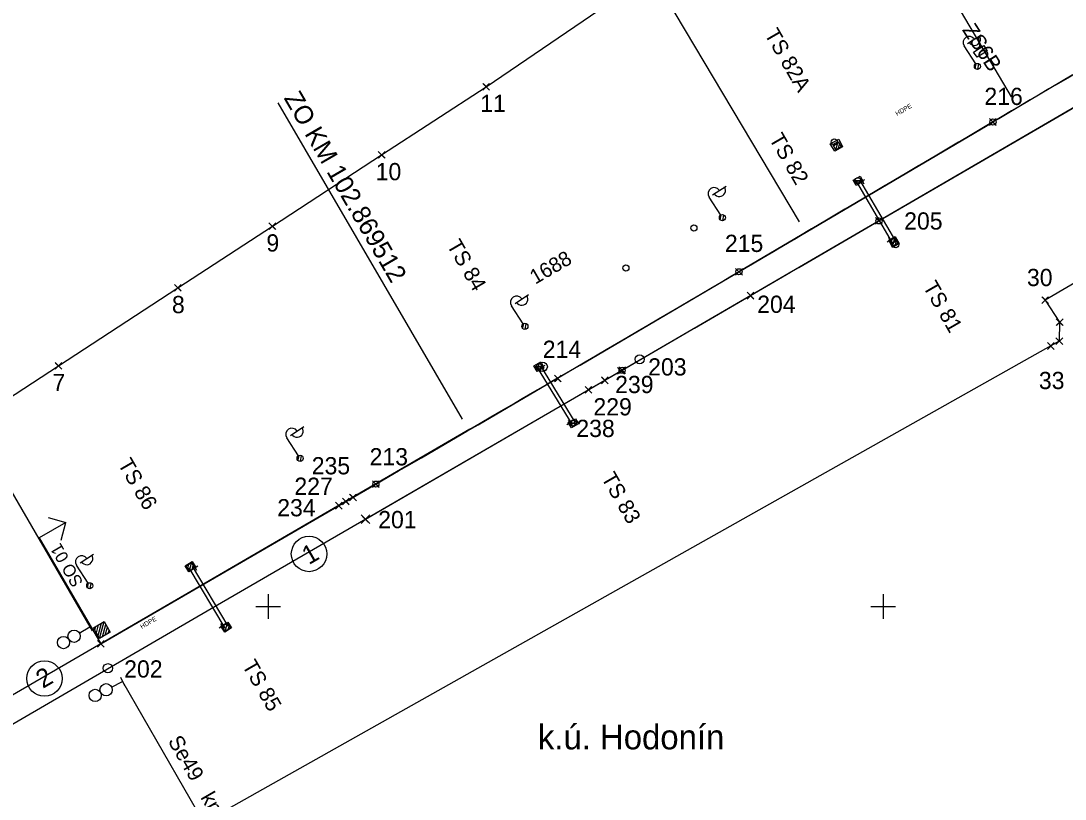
# Model space of a CAD drawing. Extents: x -566182 to -565305, y -1203073 to -1202401.
# Drawn here: x -566040.2 to -565870.4, y -1202931.3 to -1202804.8 of the extents above; entities that cross this region are included whole.
import ezdxf

# ---------------------------------------------------------------- set-up
doc = ezdxf.new("R2010")
doc.units = 0
for name, color, linetype in [('Implicitní', 7, 'Continuous'), ('LÁTAL_SVRŠEK', 7, 'Continuous'), ('PODÉLNÝ PROFIL POPIS+TENKÁ', 7, 'Continuous'), ('SZDC', 7, 'Continuous'), ('Vrstva 1', 7, 'Continuous'), ('Vrstva 10', 7, 'Continuous'), ('Vrstva 12', 7, 'Continuous'), ('Vrstva 13', 7, 'Continuous'), ('Vrstva 24', 7, 'Continuous'), ('Vrstva 25', 7, 'Continuous'), ('Vrstva 28', 7, 'Continuous'), ('Vrstva 39', 7, 'Continuous'), ('Vrstva 40', 7, 'Continuous'), ('Vrstva 42', 7, 'Continuous'), ('Vrstva 5', 7, 'Continuous'), ('Vrstva 6', 7, 'Continuous'), ('Vrstva 60', 7, 'Continuous'), ('Vrstva 62', 7, 'Continuous'), ('Vrstva 63', 7, 'Continuous'), ('Vrstva 8', 7, 'Continuous'), ('Vrstva 9', 7, 'Continuous')]:
    doc.layers.add(name, color=color, linetype=linetype)

# ---------------------------------------------------------------- blocks, each defined once
blk = doc.blocks.new('ODPOJ')
at = {"layer": 'Vrstva 62'}
blk.add_circle((0, 0), 5, dxfattribs=at)
blk = doc.blocks.new('C513')
at = {"layer": 'Vrstva 6'}
blk.add_circle((0, 0), 7.5, dxfattribs=at)
blk = doc.blocks.new('C691')
at = {"layer": 'Vrstva 12'}
for p, q in [((-5, 0), (5, 0)), ((0, 5), (0, -5))]:
    blk.add_line(p, q, dxfattribs=at)
blk = doc.blocks.new('C669')
at = {"layer": 'Vrstva 6'}
for p, q in [((0, 5), (0, 40)), ((7, 40), (33, 40)), ((-5, -1), (1, 5)), ((-2, -4), (4, 2))]:
    blk.add_line(p, q, dxfattribs=at)
blk.add_circle((0, 0), 5, dxfattribs=at)
blk.add_circle((0, 0), 5, dxfattribs=at)
for centre, start, end in [((10, 40), 0.0001, 180.0001), ((20, 39.9), 179.2975, 0.7026)]:
    blk.add_arc(centre, 10, start, end, dxfattribs=at)
blk = doc.blocks.new('C202_1')
at = {"layer": 'Vrstva 8'}
blk.add_lwpolyline([(-9.5, 0.3), (-10.2, 10.1), (10.1, 10.2), (9.5, -0.3), (-9.5, 0.3)], dxfattribs=at)
blk = doc.blocks.new('C661')
at = {"layer": 'Vrstva 12'}
for p, q in [((-5, 0.3), (-0.3, 5)), ((-5, -5), (5, 5)), ((0.3, -5), (5, -0.3))]:
    blk.add_line(p, q, dxfattribs=at)
blk.add_lwpolyline([(-5, 5), (5, 5), (5, -5), (-5, -5)], close=True, dxfattribs=at)
blk.add_lwpolyline([(-5, 5), (5, 5), (5, -5), (-5, -5), (-5, 5)], dxfattribs=at)
blk = doc.blocks.new('C661_1')
at = {"layer": 'Vrstva 12'}
for p, q in [((-5, 0.3), (-0.3, 5)), ((-5, -5), (5, 5)), ((0.3, -5), (5, -0.3))]:
    blk.add_line(p, q, dxfattribs=at)
blk.add_lwpolyline([(-5, 5), (5, 5), (5, -5), (-5, -5)], close=True, dxfattribs=at)
blk.add_lwpolyline([(-5, 5), (5, 5), (5, -5), (-5, -5), (-5, 5)], dxfattribs=at)
blk = doc.blocks.new('C661_2')
at = {"layer": 'Vrstva 12'}
for p, q in [((-5, 0.3), (-0.3, 5)), ((-5, -5), (5, 5)), ((0.3, -5), (5, -0.3))]:
    blk.add_line(p, q, dxfattribs=at)
blk.add_lwpolyline([(-5, 5), (5, 5), (5, -5), (-5, -5)], close=True, dxfattribs=at)
blk.add_lwpolyline([(-5, 5), (5, 5), (5, -5), (-5, -5), (-5, 5)], dxfattribs=at)
blk = doc.blocks.new('C651')
at = {"layer": 'Vrstva 28'}
for p, q in [((-10, -4.1), (-5.9, 0)), ((-10, -9.4), (-0.6, 0)), ((-10, -14.7), (4.7, 0)), ((-10, -20), (10, 0)), ((-4.7, -20), (10, -5.3)), ((0.6, -20), (10, -10.6)), ((5.9, -20), (10, -15.9))]:
    blk.add_line(p, q, dxfattribs=at)
blk.add_lwpolyline([(-10, 0), (10, 0), (10, -20), (-10, -20)], close=True, dxfattribs=at)
blk.add_lwpolyline([(-10, 0), (10, 0), (10, -20), (-10, -20)], close=True, dxfattribs=at)
blk.add_lwpolyline([(-10, 0), (10, 0), (10, -20), (-10, -20), (-10, 0)], dxfattribs=at)
blk.add_lwpolyline([(-10, 0), (10, 0), (10, -20), (-10, -20), (-10, 0)], dxfattribs=at)
blk = doc.blocks.new('C569_2')
at = {"layer": 'Vrstva 24'}
for p, q in [((0, -7.5), (0, 7.5)), ((20, 0), (0, 0))]:
    blk.add_line(p, q, dxfattribs=at)
for centre in [(30, 0), (50, 0)]:
    blk.add_circle(centre, 10, dxfattribs=at)
blk = doc.blocks.new('C569_3')
at = {"layer": 'Vrstva 24'}
for p, q in [((0, -7.5), (0, 7.5)), ((20, 0), (0, 0))]:
    blk.add_line(p, q, dxfattribs=at)
for centre in [(30, 0), (50, 0)]:
    blk.add_circle(centre, 10, dxfattribs=at)
blk = doc.blocks.new('ODPOJ_1')
at = {"layer": 'Vrstva 40'}
blk.add_circle((0, 0), 5, dxfattribs=at)
blk = doc.blocks.new('C562')
at = {"layer": 'Vrstva 12'}
for p, q in [((-5, 0), (5, 0)), ((-4, -3), (-1, 0)), ((-0.6, -5), (4.3, 0))]:
    blk.add_line(p, q, dxfattribs=at)
blk.add_lwpolyline([(5, 0), (-5, 0)], dxfattribs=at)
blk.add_circle((0, 0), 5.03, dxfattribs=at)
blk.add_arc((0, 0), 5.03, 180, 0, dxfattribs=at)
blk = doc.blocks.new('POINT_DISPLAY')
at = {"layer": 'Implicitní'}
for p, q in [((-0.7, -0.7), (0.7, 0.7)), ((-0.7, 0.7), (0.7, -0.7))]:
    blk.add_line(p, q, dxfattribs=at)

msp = doc.modelspace()

# ---------------------------------------------------------------- linework, layer by layer
at = {"layer": 'LÁTAL_SVRŠEK'}
for p, q in [((-565900.69, -1202837.33), (-565859.02, -1202813.09)), ((-565900.69, -1202837.33), (-565859.02, -1202813.09)), ((-565882.15, -1202821.26), (-565923.45, -1202845.6)), ((-565923.45, -1202845.6), (-565882.15, -1202821.26)), ((-565984.2, -1202885.83), (-565942.45, -1202861.6)), ((-566027.23, -1202906.08), (-565982.49, -1202880.12))]:
    msp.add_line(p, q, dxfattribs=at)
for centre in [(-565882.15, -1202821.26), (-565900.69, -1202837.33), (-565923.45, -1202845.6), (-565942.45, -1202861.6), (-565982.49, -1202880.12)]:
    msp.add_circle(centre, 0.5, dxfattribs=at)
for centre, radius, start, end in [((-560804.84, -1211436.41), 10000, 120.189547, 120.512837), ((-591042.76, -1159618.4), 50000, 300.132814, 300.188159), ((-571000.77, -1194230.45), 10000, 300.120974, 300.512837)]:
    msp.add_arc(centre, radius, start, end, dxfattribs=at)
at = {"layer": 'PODÉLNÝ PROFIL POPIS+TENKÁ'}
for centre in [(-565993.37, -1202891.47), (-566036.39, -1202911.72)]:
    msp.add_circle(centre, 2.88, dxfattribs=at)
at = {"layer": 'SZDC'}
for points in [[(-566109.86, -1202908.94), (-566097.96, -1202902.03), (-566084.51, -1202894.21), (-566065.16, -1202881.19), (-566062.89, -1202879.66), (-566050.93, -1202871.86), (-566034.12, -1202860.89), (-566014.69, -1202848.22), (-565999.33, -1202838.2), (-565981.56, -1202826.61), (-565964.56, -1202815.52), (-565946.25, -1202803.07), (-565943.74, -1202801.57), (-565935.57, -1202796.69), (-565927.13, -1202791.65), (-565924.54, -1202790.1), (-565905.03, -1202778.89), (-565894.6, -1202771.96), (-565883.49, -1202764.57), (-565860.68, -1202749.5), (-565834.73, -1202732.72)], [(-565859.38, -1202962.26), (-565861.03, -1202936.37), (-565855.35, -1202900.62), (-565842.42, -1202864.28), (-565828.48, -1202833.86), (-565823.01, -1202820.65), (-565873.65, -1202850.2), (-565871.3, -1202853.81), (-565871.36, -1202856.88), (-565872.74, -1202857.66), (-566063.99, -1202965.17)]]:
    msp.add_lwpolyline(points, dxfattribs=at)
at = {"layer": 'Vrstva 1'}
for p, q in [((-566032.9, -1202886.33), (-566037.23, -1202888.84)), ((-566035.8, -1202885.56), (-566032.9, -1202886.33)), ((-566033.67, -1202889.23), (-566032.9, -1202886.33)), ((-566037.23, -1202888.84), (-566027.23, -1202906.08))]:
    msp.add_line(p, q, dxfattribs=at)
at = {"layer": 'Vrstva 10'}
for p, q in [((-565908.63, -1202824.83), (-565907.23, -1202824.05)), ((-565907.88, -1202826), (-565908.63, -1202824.83)), ((-565906.59, -1202825.27), (-565907.88, -1202826)), ((-565907.23, -1202824.05), (-565906.59, -1202825.27)), ((-565904.89, -1202830.72), (-565903.76, -1202830.04)), ((-565903.76, -1202830.04), (-565903.28, -1202830.9)), ((-565904.41, -1202831.56), (-565904.89, -1202830.72)), ((-565903.28, -1202830.9), (-565904.41, -1202831.56)), ((-565899.1, -1202840.45), (-565898.07, -1202839.85)), ((-565898.46, -1202841.63), (-565899.1, -1202840.45)), ((-565898.07, -1202839.85), (-565897.38, -1202841.02)), ((-565897.38, -1202841.02), (-565898.46, -1202841.63)), ((-565956.82, -1202860.91), (-565955.68, -1202860.24)), ((-565956.28, -1202861.79), (-565956.82, -1202860.91)), ((-565955.68, -1202860.24), (-565955.21, -1202861.14)), ((-565955.21, -1202861.14), (-565956.28, -1202861.79)), ((-565951.21, -1202870.12), (-565950.05, -1202869.5)), ((-565950.05, -1202869.5), (-565949.57, -1202870.3)), ((-565950.7, -1202870.96), (-565951.21, -1202870.12)), ((-565949.57, -1202870.3), (-565950.7, -1202870.96)), ((-566013.49, -1202893.38), (-566012.36, -1202892.67)), ((-566012.92, -1202894.4), (-566013.49, -1202893.38)), ((-566012.36, -1202892.67), (-566011.78, -1202893.69)), ((-566011.78, -1202893.69), (-566012.92, -1202894.4)), ((-566007.72, -1202903.2), (-566006.59, -1202902.54)), ((-566007.08, -1202904.19), (-566007.72, -1202903.2)), ((-566005.96, -1202903.5), (-566007.08, -1202904.19)), ((-566006.59, -1202902.54), (-566005.96, -1202903.5))]:
    msp.add_line(p, q, dxfattribs=at)
at = {"layer": 'Vrstva 12'}
for points in [[(-565904.36, -1202830.96), (-565898.53, -1202840.91)], [(-565903.84, -1202830.66), (-565898.01, -1202840.61)], [(-565955.74, -1202860.87), (-565950.12, -1202870.04)], [(-565956.25, -1202861.18), (-565950.64, -1202870.36)], [(-566012.91, -1202893.74), (-566007.07, -1202903.52)], [(-566012.39, -1202893.43), (-566006.56, -1202903.21)]]:
    msp.add_lwpolyline(points, dxfattribs=at)
at = {"layer": 'Vrstva 5'}
for p, q in [((-566000, -1202898), (-566000, -1202902)), ((-565900, -1202898), (-565900, -1202902)), ((-566002, -1202900), (-565998, -1202900)), ((-565902, -1202900), (-565898, -1202900))]:
    msp.add_line(p, q, dxfattribs=at)
at = {"layer": 'Vrstva 6'}
for points in [[(-566068.74, -1202934.92), (-566067.2, -1202934.01), (-566009.26, -1202900.35), (-565952.55, -1202867.42), (-565900.78, -1202837.32), (-565844.77, -1202804.78), (-565792.03, -1202774.14)], [(-565967.23, -1202871.18), (-566010.28, -1202896.21), (-566069.32, -1202930.5), (-566070.86, -1202931.4)]]:
    msp.add_lwpolyline(points, dxfattribs=at)
for centre, radius, start, end in [((-561050.64, -1211005.49), 9503.95, 120.13635, 120.525886), ((-524776.56, -1272604.54), 80989.97, 120.4966194, 120.5251694), ((-572122.69, -1192292.3), 12239.38, 300.193528, 300.489147)]:
    msp.add_arc(centre, radius, start, end, dxfattribs=at)
at = {"layer": 'Vrstva 60'}
for p, q in [((-565879.13, -1202817.16), (-565911.63, -1202762.03)), ((-565913.59, -1202837.48), (-565953.43, -1202770.71)), ((-565964.11, -1202815.97), (-565965.11, -1202814.97)), ((-565964.11, -1202815.07), (-565965.11, -1202816.07)), ((-565965.01, -1202815.97), (-565964.01, -1202814.97)), ((-565965.01, -1202815.07), (-565964.01, -1202816.07)), ((-565964.56, -1202815.52), (-565964.56, -1202815.52)), ((-565968.41, -1202869.55), (-565998.4, -1202818.13)), ((-565881.7, -1202821.71), (-565882.7, -1202820.71)), ((-565881.7, -1202820.81), (-565882.7, -1202821.81)), ((-565882.6, -1202821.71), (-565881.6, -1202820.71)), ((-565882.6, -1202820.81), (-565881.6, -1202821.81)), ((-565882.15, -1202821.26), (-565882.15, -1202821.26)), ((-565981.11, -1202827.06), (-565982.11, -1202826.06)), ((-565981.11, -1202826.16), (-565982.11, -1202827.16)), ((-565982.01, -1202827.06), (-565981.01, -1202826.06)), ((-565982.01, -1202826.16), (-565981.01, -1202827.16)), ((-565981.56, -1202826.61), (-565981.56, -1202826.61)), ((-565900.24, -1202837.78), (-565901.24, -1202836.78)), ((-565900.24, -1202836.88), (-565901.24, -1202837.88)), ((-565901.14, -1202837.78), (-565900.14, -1202836.78)), ((-565901.14, -1202836.88), (-565900.14, -1202837.88)), ((-565900.69, -1202837.33), (-565900.69, -1202837.33)), ((-565998.88, -1202838.65), (-565999.88, -1202837.65)), ((-565998.88, -1202837.75), (-565999.88, -1202838.75)), ((-565999.78, -1202838.65), (-565998.78, -1202837.65)), ((-565999.78, -1202837.75), (-565998.78, -1202838.75)), ((-565999.33, -1202838.2), (-565999.33, -1202838.2)), ((-565923, -1202846.05), (-565924, -1202845.05)), ((-565923, -1202845.15), (-565924, -1202846.15)), ((-565923.9, -1202846.05), (-565922.9, -1202845.05)), ((-565923.9, -1202845.15), (-565922.9, -1202846.15)), ((-565923.45, -1202845.6), (-565923.45, -1202845.6)), ((-566014.24, -1202848.67), (-566015.24, -1202847.67)), ((-566014.24, -1202847.77), (-566015.24, -1202848.77)), ((-566015.14, -1202848.67), (-566014.14, -1202847.67)), ((-566015.14, -1202847.77), (-566014.14, -1202848.77)), ((-566014.69, -1202848.22), (-566014.69, -1202848.22)), ((-565921.11, -1202849.93), (-565922.11, -1202848.93)), ((-565921.11, -1202849.03), (-565922.11, -1202850.03)), ((-565922.01, -1202849.93), (-565921.01, -1202848.93)), ((-565922.01, -1202849.03), (-565921.01, -1202850.03)), ((-565921.56, -1202849.48), (-565921.56, -1202849.48)), ((-565873.2, -1202850.65), (-565874.2, -1202849.65)), ((-565873.2, -1202849.75), (-565874.2, -1202850.75)), ((-565874.1, -1202850.65), (-565873.1, -1202849.65)), ((-565874.1, -1202849.75), (-565873.1, -1202850.75)), ((-565873.65, -1202850.2), (-565873.65, -1202850.2)), ((-566058.78, -1202852.05), (-566029.01, -1202903.3)), ((-565870.85, -1202854.26), (-565871.85, -1202853.26)), ((-565870.85, -1202853.36), (-565871.85, -1202854.36)), ((-565871.75, -1202854.26), (-565870.75, -1202853.26)), ((-565871.75, -1202853.36), (-565870.75, -1202854.36)), ((-565871.3, -1202853.81), (-565871.3, -1202853.81)), ((-565872.29, -1202858.11), (-565873.29, -1202857.11)), ((-565872.29, -1202857.21), (-565873.29, -1202858.21)), ((-565873.19, -1202858.11), (-565872.19, -1202857.11)), ((-565873.19, -1202857.21), (-565872.19, -1202858.21)), ((-565872.74, -1202857.66), (-565872.74, -1202857.66)), ((-565870.91, -1202857.33), (-565871.91, -1202856.33)), ((-565870.91, -1202856.43), (-565871.91, -1202857.43)), ((-565871.81, -1202857.33), (-565870.81, -1202856.33)), ((-565871.81, -1202856.43), (-565870.81, -1202857.43)), ((-565871.36, -1202856.88), (-565871.36, -1202856.88)), ((-566033.67, -1202861.34), (-566034.67, -1202860.34)), ((-566033.67, -1202860.44), (-566034.67, -1202861.44)), ((-566034.57, -1202861.34), (-566033.57, -1202860.34)), ((-566034.57, -1202860.44), (-566033.57, -1202861.44)), ((-566034.12, -1202860.89), (-566034.12, -1202860.89)), ((-565942, -1202862.05), (-565943, -1202861.05)), ((-565942.9, -1202862.05), (-565941.9, -1202861.05)), ((-565952.46, -1202863.41), (-565953.46, -1202862.41)), ((-565952.46, -1202862.51), (-565953.46, -1202863.51)), ((-565953.36, -1202863.41), (-565952.36, -1202862.41)), ((-565953.36, -1202862.51), (-565952.36, -1202863.51)), ((-565944.83, -1202863.69), (-565945.83, -1202862.69)), ((-565944.83, -1202862.79), (-565945.83, -1202863.79)), ((-565945.73, -1202863.69), (-565944.73, -1202862.69)), ((-565945.73, -1202862.79), (-565944.73, -1202863.79)), ((-565942.18, -1202862.16), (-565943.18, -1202861.16)), ((-565942.18, -1202861.26), (-565943.18, -1202862.26)), ((-565943.08, -1202862.16), (-565942.08, -1202861.16)), ((-565943.08, -1202861.26), (-565942.08, -1202862.26)), ((-565942, -1202861.15), (-565943, -1202862.15)), ((-565942.9, -1202861.15), (-565941.9, -1202862.15)), ((-565942.63, -1202861.71), (-565942.63, -1202861.71)), ((-565942.45, -1202861.6), (-565942.45, -1202861.6)), ((-565952.91, -1202862.96), (-565952.91, -1202862.96)), ((-565947.48, -1202865.23), (-565948.48, -1202864.23)), ((-565947.48, -1202864.33), (-565948.48, -1202865.33)), ((-565948.39, -1202865.23), (-565947.39, -1202864.23)), ((-565948.39, -1202864.33), (-565947.39, -1202865.33)), ((-565945.28, -1202863.24), (-565945.28, -1202863.24)), ((-565947.94, -1202864.78), (-565947.94, -1202864.78)), ((-565982.04, -1202880.57), (-565983.04, -1202879.57)), ((-565982.04, -1202879.67), (-565983.04, -1202880.67)), ((-565982.94, -1202880.57), (-565981.94, -1202879.57)), ((-565982.94, -1202879.67), (-565981.94, -1202880.67)), ((-565982.49, -1202880.12), (-565982.49, -1202880.12)), ((-565988.07, -1202884.07), (-565989.07, -1202883.07)), ((-565988.07, -1202883.17), (-565989.07, -1202884.17)), ((-565988.97, -1202884.07), (-565987.97, -1202883.07)), ((-565988.97, -1202883.17), (-565987.97, -1202884.17)), ((-565986.92, -1202883.4), (-565987.92, -1202882.4)), ((-565986.92, -1202882.5), (-565987.92, -1202883.5)), ((-565987.82, -1202883.4), (-565986.82, -1202882.4)), ((-565987.82, -1202882.5), (-565986.82, -1202883.5)), ((-565987.37, -1202882.95), (-565987.37, -1202882.95)), ((-565985.77, -1202882.74), (-565986.77, -1202881.74)), ((-565985.77, -1202881.83), (-565986.77, -1202882.83)), ((-565986.67, -1202882.74), (-565985.67, -1202881.74)), ((-565986.67, -1202881.83), (-565985.67, -1202882.83)), ((-565986.22, -1202882.28), (-565986.22, -1202882.28)), ((-565988.52, -1202883.62), (-565988.52, -1202883.62)), ((-565983.75, -1202886.28), (-565984.75, -1202885.28)), ((-565983.75, -1202885.38), (-565984.75, -1202886.38)), ((-565984.65, -1202886.28), (-565983.65, -1202885.28)), ((-565984.65, -1202885.38), (-565983.65, -1202886.38)), ((-565984.2, -1202885.83), (-565984.2, -1202885.83)), ((-566026.78, -1202906.53), (-566027.78, -1202905.53)), ((-566026.78, -1202905.63), (-566027.78, -1202906.63)), ((-566027.68, -1202906.53), (-566026.68, -1202905.53)), ((-566027.68, -1202905.63), (-566026.68, -1202906.63)), ((-566027.23, -1202906.08), (-566027.23, -1202906.08)), ((-566023.69, -1202912.19), (-565996.16, -1202959.95))]:
    msp.add_line(p, q, dxfattribs=at)
at = {"layer": 'Vrstva 63'}
msp.add_line((-565955.41, -1202861.06), (-565955.32, -1202861.01), dxfattribs=at)
msp.add_circle((-565955.37, -1202861.04), 0.756, dxfattribs=at)

# ---------------------------------------------------------------- block references
at = {"layer": 'LÁTAL_SVRŠEK'}
msp.add_blockref('POINT_DISPLAY', (-565984.2, -1202885.83), dxfattribs=at)
at = {"layer": 'Vrstva 12'}
for name, p, xscale, yscale, rotation in [('C661_2', (-565907.53, -1202825.08), 0.10000006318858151, 0.10000006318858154, 29.57266490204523), ('C691', (-565903.4, -1202830.85), 0.09999990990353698, 0.09999990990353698, 30.000029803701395), ('C691', (-565898.91, -1202840.46), 0.09999990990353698, 0.09999990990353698, 30.000029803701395), ('C661_1', (-565898.27, -1202840.76), 0.09999974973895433, 0.09999974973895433, 30.15054033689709), ('C691', (-565955.41, -1202861.01), 0.09999990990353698, 0.09999990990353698, 30.000029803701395), ('C691', (-565950.99, -1202870.16), 0.09999990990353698, 0.09999990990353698, 30.000029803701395), ('C661', (-566012.65, -1202893.58), 0.10000021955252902, 0.10000021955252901, 30.801732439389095), ('C691', (-566011.9, -1202893.67), 0.09999990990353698, 0.09999990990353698, 30.000029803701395), ('C691', (-566007.54, -1202903.21), 0.09999990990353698, 0.09999990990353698, 30.000029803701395), ('C661', (-566006.81, -1202903.37), 0.10000021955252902, 0.10000021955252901, 30.801732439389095)]:
    msp.add_blockref(name, p, dxfattribs=dict(at, xscale=xscale, yscale=yscale, rotation=rotation))
at = {"layer": 'Vrstva 12', "xscale": 0.1, "yscale": 0.10000000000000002}
for p in [(-565904.1, -1202830.81), (-565955.99, -1202861.02), (-565950.38, -1202870.2)]:
    msp.add_blockref('C562', p, dxfattribs=at)
at = {"layer": 'Vrstva 24'}
for name, p, xscale, yscale, rotation in [('C569_2', (-566029.01, -1202903.3), 0.10000014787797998, 0.10000014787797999, -149.01231278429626), ('C569_3', (-566023.69, -1202912.19), 0.09999987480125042, 0.09999987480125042, -153.00491966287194)]:
    msp.add_blockref(name, p, dxfattribs=dict(at, xscale=xscale, yscale=yscale, rotation=rotation))
at = {"layer": 'Vrstva 28', "xscale": 0.09999990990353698, "yscale": 0.09999990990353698, "rotation": 30.000029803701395}
msp.add_blockref('C651', (-566027.55, -1202902.97), dxfattribs=at)
at = {"layer": 'Vrstva 40', "xscale": 0.1, "yscale": 0.10000000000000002}
for p in [(-565907.95, -1202824.51), (-565930.78, -1202838.49), (-565897.95, -1202841.19), (-565941.84, -1202844.99)]:
    msp.add_blockref('ODPOJ_1', p, dxfattribs=at)
at = {"layer": 'Vrstva 6'}
for name, p, xscale, yscale, rotation in [('C669', (-565884.67, -1202812.23), 0.10000003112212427, 0.10000003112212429, 32.99994277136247), ('C669', (-565926.14, -1202836.81), 0.10000003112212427, 0.10000003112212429, 32.99994277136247), ('C669', (-565958.27, -1202854.47), 0.10000003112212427, 0.10000003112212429, 32.99994277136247), ('C513', (-565939.6, -1202859.83), 0.1, 0.10000000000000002, 180), ('C669', (-565994.81, -1202875.93), 0.10000003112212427, 0.10000003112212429, 32.99994277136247), ('C669', (-566029.02, -1202896.65), 0.10000003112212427, 0.10000003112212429, 32.99994277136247), ('C513', (-566026.08, -1202910.05), 0.1, 0.10000000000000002, 180)]:
    msp.add_blockref(name, p, dxfattribs=dict(at, xscale=xscale, yscale=yscale, rotation=rotation))
at = {"layer": 'Vrstva 62', "xscale": 0.1, "yscale": 0.10000000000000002}
for p in [(-565907.95, -1202824.51), (-565930.78, -1202838.49), (-565897.95, -1202841.19), (-565941.84, -1202844.99)]:
    msp.add_blockref('ODPOJ', p, dxfattribs=at)
at = {"layer": 'Vrstva 8', "xscale": 0.10000003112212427, "yscale": 0.10000003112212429, "rotation": 32.99994277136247}
msp.add_blockref('C202_1', (-565883.92, -1202810.22), dxfattribs=at)

# ---------------------------------------------------------------- texts
at = {"layer": 'PODÉLNÝ PROFIL POPIS+TENKÁ'}
for s, p in [('1', (-565993.4, -1202893.3)), ('2', (-566036.66, -1202913.41))]:
    msp.add_text(s, height=3, rotation=30.1392, dxfattribs=at).set_placement(p)
at = {"layer": 'Vrstva 1'}
msp.add_text('SO 01', height=2, rotation=120.121, dxfattribs=at).set_placement((-566030.03, -1202896.11))
msp.add_text('k.ú. Hodonín', height=4, dxfattribs=at).set_placement((-565956.16, -1202923.23))
at = {"layer": 'Vrstva 13'}
for s, p in [('TS 82A', (-565919.37, -1202806.96)), ('TS 82', (-565918.62, -1202823.97)), ('TS 84', (-565971.03, -1202841.27)), ('TS 81', (-565893.61, -1202848.01)), ('TS 86', (-566024.52, -1202876.84)), ('TS 83', (-565945.91, -1202879.09)), ('TS 85', (-566004.32, -1202909.59))]:
    msp.add_text(s, height=2.5, rotation=300, dxfattribs=at).set_placement(p)
at = {"layer": 'Vrstva 25'}
msp.add_text('Se49   km 102.801', height=2.5, rotation=299.9873, dxfattribs=at).set_placement((-566016.39, -1202921.87))
at = {"layer": 'Vrstva 39'}
msp.add_text('ZO KM 102.869512', height=3, rotation=300.153, dxfattribs=at).set_placement((-565997.53, -1202817.36))
at = {"layer": 'Vrstva 42'}
for rotation, p in [(30.1551, (-565897.74, -1202820.3)), (30.1468, (-566020.56, -1202903.67))]:
    msp.add_text('HDPE', height=0.75, rotation=rotation, dxfattribs=at).set_placement(p)
at = {"layer": 'Vrstva 60'}
for s, p in [('11', (-565965.53, -1202819.63)), ('216', (-565883.54, -1202818.49)), ('10', (-565982.53, -1202830.72)), ('205', (-565896.59, -1202838.74)), ('9', (-566000.3, -1202842.31)), ('215', (-565925.74, -1202842.38)), ('30', (-565876.62, -1202847.93)), ('8', (-566015.66, -1202852.33)), ('204', (-565920.49, -1202852.28)), ('214', (-565955.36, -1202859.6)), ('203', (-565938.22, -1202862.46)), ('7', (-566035.09, -1202865)), ('239', (-565943.59, -1202865.32)), ('33', (-565874.68, -1202864.67)), ('229', (-565947.12, -1202868.95)), ('238', (-565949.9, -1202872.46)), ('213', (-565983.52, -1202877.07)), ('235', (-565992.93, -1202878.53)), ('227', (-565995.75, -1202881.86)), ('234', (-565998.54, -1202885.35)), ('201', (-565982.12, -1202887.28)), ('202', (-566023.43, -1202911.56))]:
    msp.add_text(s, height=2.8, dxfattribs=at).set_placement(p)
at = {"layer": 'Vrstva 63'}
msp.add_text('1688', height=2.4, rotation=30.1679, dxfattribs=at).set_placement((-565956.58, -1202847.71))
at = {"layer": 'Vrstva 9'}
msp.add_text('ZS6B', height=2.5, rotation=303, dxfattribs=at).set_placement((-565887.23, -1202806.28))

doc.saveas('drawing.dxf')
